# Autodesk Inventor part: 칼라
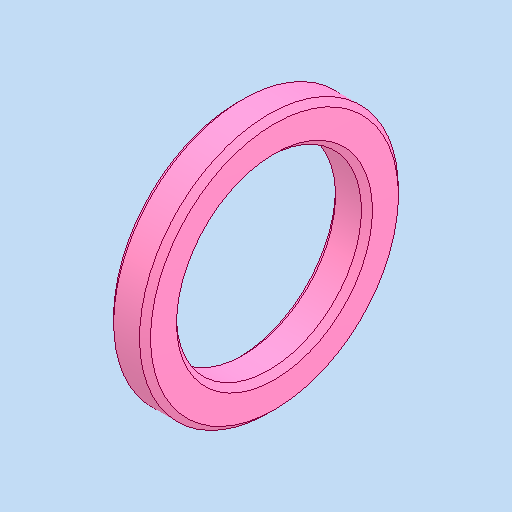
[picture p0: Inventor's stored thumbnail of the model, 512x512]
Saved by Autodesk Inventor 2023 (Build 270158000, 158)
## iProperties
Created: 2026-04
Part Number: 칼라
Material: 강철, 연강
Document SubType Name: Modeling
Designer: home
Density: 7.85 g/cm^3
Appearance: 기본값
Author: jhkim
Sending System: Autodesk Inventor 2027
Preprocessor: ST-DEVELOPER v20.1
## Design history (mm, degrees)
feature "솔리드1"
node "솔리드2"
